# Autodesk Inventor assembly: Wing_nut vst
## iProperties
Shininess: 20.0
Length Units: 11269
Angle Units: 11279
Time Units: 11290
Mass Units: 11283
Length Display Precision: 3
Angle Display Precision: 2
Created: 2001-04
Part Number: Wing_nut vst
Document SubType Name: Baugruppe
Designer: dl
Density: 0.0
Volumn: 0.0
Area: 0.0
PropertySet Name: Model Information
Control State: 0
Master: False
Checked Out: False
Author: dl
